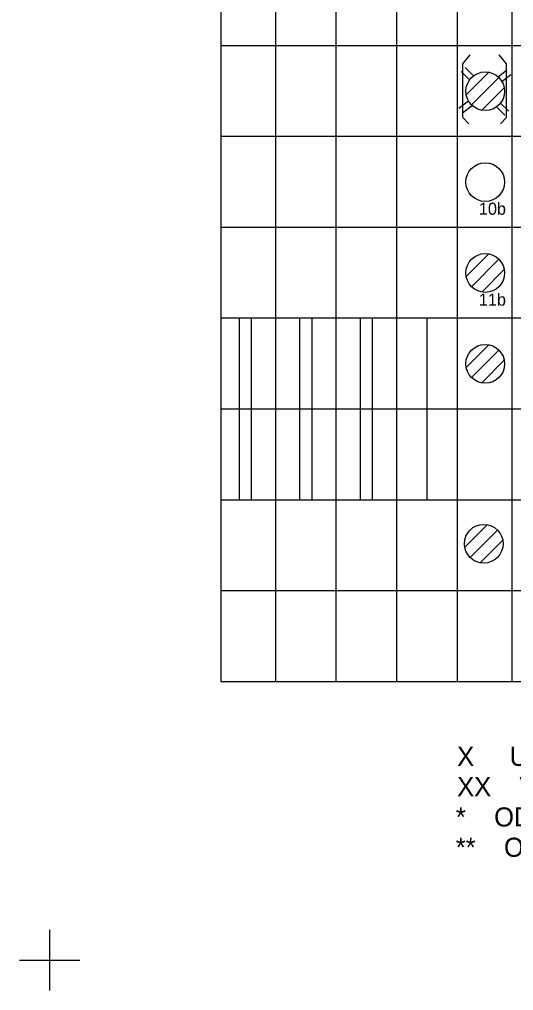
# Model space of a CAD drawing. Extents: x -28 to 822, y 61 to 665.
# Drawn here: x -28.2 to 53.4, y 60.7 to 221 of the extents above; entities that cross this region are included whole.
import ezdxf

# ---------------------------------------------------------------- set-up
doc = ezdxf.new("R2010")
doc.units = 0
for name, color, linetype in [('KOLEJIŠTĚ', 7, 'Continuous'), ('nové', 7, 'Continuous'), ('Vrstva 60', 7, 'Continuous')]:
    doc.layers.add(name, color=color, linetype=linetype)

# ---------------------------------------------------------------- blocks, each defined once
blk = doc.blocks.new('ZT95')
for p, q in [((2.793, 4.073), (0.927, 2.207)), ((3.631, 3.631), (1.369, 1.369)), ((4.073, 2.793), (2.207, 0.927))]:
    blk.add_line(p, q)
blk.add_circle((2.5, 2.5), 1.6)

msp = doc.modelspace()

# ---------------------------------------------------------------- linework, layer by layer
for p, q in [((5.07, 381.74), (5.07, 111.74)), ((14.09, 381.74), (14.09, 111.74)), ((24.09, 381.74), (24.09, 111.74)), ((34.09, 381.74), (34.09, 111.74)), ((53.12, 381.74), (53.12, 111.74)), ((44.09, 336.74), (44.09, 111.74)), ((5.07, 216.74), (540.62, 216.74)), ((45.05, 213.68), (46.25, 215.15)), ((52.23, 213.68), (51.03, 215.15)), ((45.05, 204.87), (45.05, 213.68)), ((52.23, 204.87), (52.23, 213.68)), ((46.14, 211.05), (44.78, 212.41)), ((46.79, 211.71), (45.43, 213.06)), ((50.89, 211.54), (52.33, 212.7)), ((51.5, 210.78), (52.95, 211.94)), ((44.39, 206.35), (45.95, 207.6)), ((45, 205.58), (46.56, 206.83)), ((52.63, 205.86), (51.27, 207.22)), ((51.98, 205.21), (50.61, 206.58)), ((45.03, 204.84), (46.03, 203.76)), ((52.25, 204.84), (51.25, 203.76)), ((5.07, 201.74), (540.62, 201.74)), ((5.07, 201.74), (540.62, 201.74)), ((5.07, 201.74), (540.62, 201.74)), ((5.07, 186.74), (295.62, 186.74)), ((5.07, 171.74), (540.62, 171.74)), ((5.07, 156.74), (295.62, 156.74)), ((5.07, 141.74), (540.62, 141.74)), ((5.07, 126.74), (293.12, 126.74)), ((5.07, 111.74), (540.62, 111.74))]:
    msp.add_line(p, q)
msp.add_circle((48.74, 194.17), 3.2)
at = {"layer": 'nové'}
for p, q in [((8.09, 171.74), (8.09, 156.74)), ((10.09, 171.74), (10.09, 156.74)), ((18.09, 171.74), (18.09, 156.74)), ((20.09, 171.74), (20.09, 156.74)), ((28.09, 171.74), (28.09, 156.74)), ((30.09, 171.74), (30.09, 156.74)), ((39.09, 171.74), (39.09, 156.74)), ((8.09, 156.74), (8.09, 141.74)), ((10.09, 156.74), (10.09, 141.74)), ((18.09, 156.74), (18.09, 141.74)), ((20.09, 156.74), (20.09, 141.74)), ((28.09, 156.74), (28.09, 141.74)), ((30.09, 156.74), (30.09, 141.74)), ((39.09, 156.74), (39.09, 141.74))]:
    msp.add_line(p, q, dxfattribs=at)
at = {"layer": 'Vrstva 60'}
for p, q in [((-23.19, 60.73), (-23.19, 70.73)), ((-28.19, 65.73), (-18.19, 65.73))]:
    msp.add_line(p, q, dxfattribs=at)

# ---------------------------------------------------------------- block references
at = {"layer": 'KOLEJIŠTĚ', "xscale": 2, "yscale": 2}
for p in [(43.74, 204.17), (43.74, 174.17), (43.74, 159.17), (43.5, 129.48)]:
    msp.add_blockref('ZT95', p, dxfattribs=at)

# ---------------------------------------------------------------- texts
for s, height, p in [('10b', 2, (47.7, 188.78)), ('11b', 2, (47.7, 173.78)), ('X     UZAMČENÍ POHONU ZÁVOR V UZAVŘENÉ POLOZE', 3.1505, (44.1, 97.81)), ('XX    VLOŽENÍ KLÍČE OD POHONU ZÁVOR DO EMZ A UZAMČENÍ ', 3.1505, (44.1, 92.81)), ('*    ODEMKNUTÍ EMZ A UVOLNĚNÍ KLÍČE PRO ZÁMEK V POHONU ZÁVOR', 3.1505, (43.89, 87.81)), ('**    ODEMKNUTÍ POHONU ZÁVOR A OTEVŘENÍ ZÁVOR', 3.1505, (43.88, 82.81))]:
    msp.add_text(s, height=height).set_placement(p)

doc.saveas('drawing.dxf')
